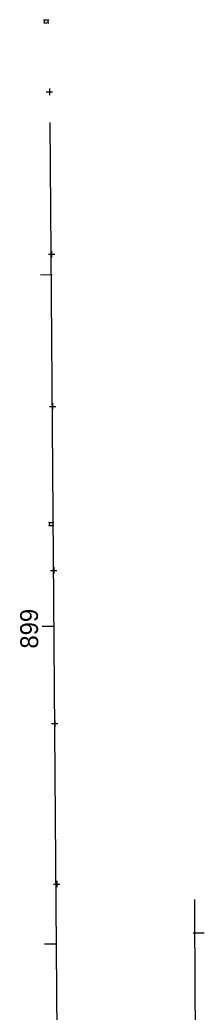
# Model space of a CAD drawing. Extents: x 1546689 to 1550004, y 741079 to 745265.
# Drawn here: x 1548822.8 to 1548851.8, y 745108.8 to 745265 of the extents above; entities that cross this region are included whole.
import ezdxf

# ---------------------------------------------------------------- set-up
doc = ezdxf.new("R2010")
doc.units = 0
for name, color, linetype in [('BR_P_Brg_Pad_Hidden', 7, 'Continuous'), ('BR_P_Det_Hidden', 7, 'Continuous'), ('BR_P_Gen_Waterproofing', 7, 'Continuous'), ('BR_P_Slab_Const_Joint', 7, 'Continuous'), ('XS_P_Subgrade', 7, 'Continuous')]:
    doc.layers.add(name, color=color, linetype=linetype)

msp = doc.modelspace()

# ---------------------------------------------------------------- linework, layer by layer
at = {"layer": 'BR_P_Brg_Pad_Hidden'}
msp.add_lwpolyline([(1548851.76, 744992.56), (1548851.61, 745010.4), (1548851.36, 745035.19), (1548851.08, 745060.57), (1548850.71, 745084.89), (1548850.44, 745111.26), (1548850.35, 745126.51)], dxfattribs=at)
at = {"layer": 'BR_P_Det_Hidden'}
for p, q in [((1548827.57, 745248.79), (1548832.82, 744559.56)), ((1548826.07, 745224.86), (1548827.9, 745224.87)), ((1548826.35, 745169.54), (1548828.17, 745169.55)), ((1548826.73, 745119.54), (1548828.55, 745119.55))]:
    msp.add_line(p, q, dxfattribs=at)
at = {"layer": 'BR_P_Gen_Waterproofing'}
for p, q in [((1548826.6, 745264.97), (1548826.7, 745264.97)), ((1548826.6, 745264.48), (1548826.7, 745264.48)), ((1548826.76, 745264.97), (1548826.86, 745264.97)), ((1548826.76, 745264.48), (1548826.86, 745264.48)), ((1548826.93, 745264.97), (1548827.03, 745264.97)), ((1548826.93, 745264.48), (1548827.03, 745264.48)), ((1548826.98, 745264.72), (1548826.98, 745264.72)), ((1548827.1, 745264.97), (1548827.2, 745264.97)), ((1548827.1, 745264.48), (1548827.2, 745264.48)), ((1548827.27, 745264.97), (1548827.37, 745264.97)), ((1548827.27, 745264.48), (1548827.37, 745264.48)), ((1548827.39, 745185.86), (1548827.49, 745185.86)), ((1548827.39, 745185.37), (1548827.49, 745185.37)), ((1548827.56, 745185.86), (1548827.66, 745185.86)), ((1548827.56, 745185.37), (1548827.66, 745185.37)), ((1548827.73, 745185.86), (1548827.83, 745185.86)), ((1548827.73, 745185.37), (1548827.83, 745185.37)), ((1548827.78, 745185.62), (1548827.78, 745185.62)), ((1548827.89, 745185.86), (1548827.99, 745185.86)), ((1548827.89, 745185.37), (1548827.99, 745185.37)), ((1548828.06, 745185.86), (1548828.16, 745185.86)), ((1548828.06, 745185.37), (1548828.16, 745185.37))]:
    msp.add_line(p, q, dxfattribs=at)
for centre, start, end in [((1548826.44, 745264.72), 42.0847, 58.0262), ((1548826.44, 745264.72), 301.9738, 317.9205), ((1548826.44, 745264.72), 18.8878, 34.8207), ((1548826.44, 745264.72), 325.1782, 341.1111), ((1548826.44, 745264.72), 348.3904, 11.6202), ((1548827.52, 745264.72), 168.3816, 191.6091), ((1548827.52, 745264.72), 145.1782, 161.1098), ((1548827.52, 745264.72), 198.8872, 214.8207), ((1548827.52, 745264.72), 121.9738, 137.9163), ((1548827.52, 745264.72), 222.0817, 238.0262), ((1548827.24, 745185.62), 42.0847, 58.0262), ((1548827.24, 745185.62), 301.9738, 317.9205), ((1548827.24, 745185.62), 18.8878, 34.8207), ((1548827.24, 745185.62), 325.1782, 341.1111), ((1548827.24, 745185.62), 348.3904, 11.6202), ((1548828.31, 745185.62), 168.3816, 191.6091), ((1548828.31, 745185.62), 145.1782, 161.1098), ((1548828.31, 745185.62), 198.8872, 214.8207), ((1548828.31, 745185.62), 121.9738, 137.9163), ((1548828.31, 745185.62), 222.0817, 238.0262)]:
    msp.add_arc(centre, 0.288, start, end, dxfattribs=at)
at = {"layer": 'BR_P_Slab_Const_Joint'}
for p, q in [((1548826.98, 745253.64), (1548827.98, 745253.64)), ((1548827.48, 745254.14), (1548827.48, 745253.14)), ((1548827.48, 745253.64), (1548827.48, 745253.64)), ((1548827.82, 745228.58), (1548827.82, 745227.58)), ((1548827.32, 745228.08), (1548828.32, 745228.08)), ((1548827.82, 745228.08), (1548827.82, 745228.08)), ((1548827.48, 745204.12), (1548828.48, 745204.12)), ((1548827.98, 745204.62), (1548827.98, 745203.62)), ((1548827.98, 745204.12), (1548827.98, 745204.12)), ((1548828.16, 745178.82), (1548828.16, 745177.82)), ((1548828.16, 745178.82), (1548828.16, 745177.82)), ((1548827.66, 745178.32), (1548828.66, 745178.32)), ((1548827.66, 745178.32), (1548828.66, 745178.32)), ((1548828.16, 745178.32), (1548828.16, 745178.32)), ((1548828.16, 745178.32), (1548828.16, 745178.32)), ((1548827.82, 745154.22), (1548828.82, 745154.22)), ((1548828.32, 745154.72), (1548828.32, 745153.72)), ((1548828.32, 745154.22), (1548828.32, 745154.22)), ((1548828.13, 745128.95), (1548829.13, 745128.95)), ((1548828.63, 745129.45), (1548828.63, 745128.45)), ((1548828.63, 745128.95), (1548828.63, 745128.95))]:
    msp.add_line(p, q, dxfattribs=at)
at = {"layer": 'XS_P_Subgrade'}
msp.add_line((1548850.11, 745121.29), (1548851.83, 745121.29), dxfattribs=at)

# ---------------------------------------------------------------- texts
at = {"layer": 'BR_P_Det_Hidden'}
msp.add_text('899', height=2.8, rotation=90.436, dxfattribs=at).set_placement((1548825.72, 745166.03))

doc.saveas('drawing.dxf')
